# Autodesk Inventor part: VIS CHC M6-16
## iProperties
Created: 2004-11
Part Number: VIS CHC M6-16
Document SubType Name: Modeling
Designer: Bruno
Manufacturer: Standard
Standards Organization: Custom
Author: Bruno
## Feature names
1. Base1
